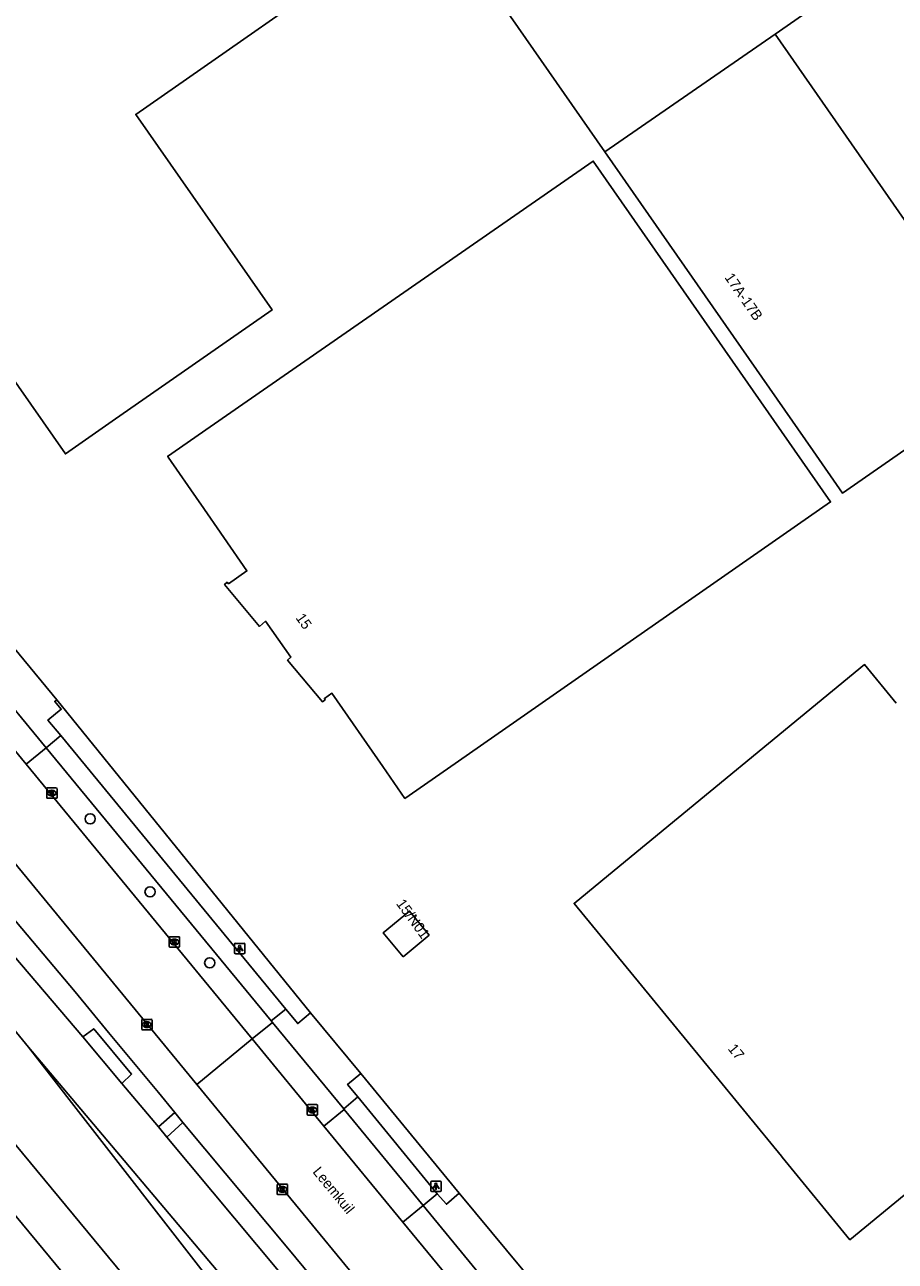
# Model space of a CAD drawing. Extents: x 156651 to 158072, y 387631 to 388990.
# Drawn here: x 157151.7 to 157235.7, y 387850.9 to 387970.3 of the extents above; entities that cross this region are included whole.
import ezdxf

# ---------------------------------------------------------------- set-up
doc = ezdxf.new("R2010")
doc.units = 0
for name, color, linetype in [('IMGEO_Berm_groen', 7, 'Continuous'), ('IMGEO_Boom', 7, 'Continuous'), ('IMGEO_Grasland_overig', 7, 'Continuous'), ('IMGEO_Groenvoorziening', 7, 'Continuous'), ('IMGEO_Kolk', 7, 'Continuous'), ('IMGEO_Lichtpunt', 7, 'Continuous'), ('IMGEO_Muur', 7, 'Continuous'), ('IMGEO_Openbare_ruimte_label', 7, 'Continuous'), ('IMGEO_Pand', 7, 'Continuous'), ('IMGEO_Pand_nummerreeks', 7, 'Continuous'), ('IMGEO_Rijbaan_lokaal_gesloten', 7, 'Continuous'), ('IMGEO_Spoor', 7, 'Continuous'), ('IMGEO_Spoorbaan_halfverhard', 7, 'Continuous'), ('IMGEO_Voetpad_open', 7, 'Continuous')]:
    doc.layers.add(name, color=color, linetype=linetype)

msp = doc.modelspace()

# ---------------------------------------------------------------- linework, layer by layer
at = {"layer": 'IMGEO_Berm_groen'}
for points in [[(157097.86, 387946.26), (157101.16, 387942.42), (157102.79, 387940.5), (157114.27, 387927.11), (157115.96, 387925.21), (157120.79, 387919.43), (157132.18, 387905.88), (157138.68, 387898.17), (157156.55, 387876.96), (157159.78, 387873.03), (157164.59, 387867.23), (157166.18, 387865.29)], [(157166.18, 387865.29), (157166.96, 387864.35)], [(157166.96, 387864.35), (157177.25, 387852.02), (157242.39, 387773.24), (157261.6, 387750), (157335.27, 387660.72)]]:
    msp.add_lwpolyline(points, dxfattribs=at)
at = {"layer": 'IMGEO_Boom'}
for centre in [(157158.01, 387893.65), (157163.79, 387886.6), (157169.55, 387879.75)]:
    msp.add_circle(centre, 0.489, dxfattribs=at)
at = {"layer": 'IMGEO_Grasland_overig'}
for points in [[(157157.31, 387872.59), (157158.35, 387873.39), (157162.01, 387869.01), (157161.07, 387868.11)], [(157164.59, 387863.91), (157166.18, 387865.29)], [(157166.96, 387864.35), (157165.42, 387862.91)]]:
    msp.add_lwpolyline(points, dxfattribs=at)
at = {"layer": 'IMGEO_Groenvoorziening'}
for points in [[(157179.28, 387874.93), (157154.78, 387905.14)], [(157193.64, 387857.52), (157184.13, 387869.06)]]:
    msp.add_lwpolyline(points, dxfattribs=at)
at = {"layer": 'IMGEO_Kolk'}
for p, q in [((157153.81, 387895.71), (157153.81, 387896.56)), ((157153.89, 387896.63), (157154.74, 387896.63)), ((157154.3, 387896.41), (157154.33, 387896.41)), ((157154.81, 387896.56), (157154.81, 387895.71)), ((157154.74, 387895.63), (157153.89, 387895.63)), ((157154.32, 387895.85), (157154.3, 387895.85)), ((157165.64, 387881.34), (157165.64, 387882.19)), ((157165.72, 387882.27), (157166.57, 387882.27)), ((157166.13, 387882.04), (157166.16, 387882.04)), ((157166.64, 387882.19), (157166.64, 387881.34)), ((157166.57, 387881.26), (157165.72, 387881.26)), ((157166.15, 387881.49), (157166.13, 387881.49)), ((157162.98, 387873.36), (157162.98, 387874.22)), ((157163.05, 387874.29), (157163.91, 387874.29)), ((157163.49, 387873.51), (157163.46, 387873.51)), ((157163.47, 387874.07), (157163.49, 387874.07)), ((157163.98, 387874.22), (157163.98, 387873.36)), ((157163.91, 387873.29), (157163.05, 387873.29)), ((157178.96, 387865.13), (157178.96, 387865.98)), ((157179.04, 387866.06), (157179.89, 387866.06)), ((157179.45, 387865.83), (157179.47, 387865.83)), ((157179.47, 387865.28), (157179.45, 387865.28)), ((157179.96, 387865.98), (157179.96, 387865.13)), ((157179.89, 387865.05), (157179.04, 387865.05)), ((157176.07, 387857.45), (157176.07, 387858.31)), ((157176.14, 387858.38), (157177, 387858.38)), ((157176.56, 387858.16), (157176.58, 387858.16)), ((157177.07, 387858.31), (157177.07, 387857.45)), ((157177, 387857.38), (157176.14, 387857.38)), ((157176.58, 387857.6), (157176.55, 387857.6))]:
    msp.add_line(p, q, dxfattribs=at)
for points in [[(157153.81, 387895.71), (157153.81, 387896.56)], [(157153.89, 387896.63), (157154.74, 387896.63)], [(157154.13, 387896.33), (157154.26, 387896.33), (157154.26, 387896.18), (157154.39, 387896.33), (157154.55, 387896.33), (157154.41, 387896.18), (157154.56, 387895.93), (157154.41, 387895.93), (157154.32, 387896.1), (157154.26, 387896.03), (157154.26, 387895.93), (157154.13, 387895.93), (157154.13, 387896.33)], [(157154.81, 387896.56), (157154.81, 387895.71)], [(157154.74, 387895.63), (157153.89, 387895.63)], [(157165.64, 387881.34), (157165.64, 387882.19)], [(157165.72, 387882.27), (157166.57, 387882.27)], [(157165.96, 387881.96), (157166.09, 387881.96), (157166.09, 387881.81), (157166.22, 387881.96), (157166.38, 387881.96), (157166.24, 387881.81), (157166.39, 387881.56), (157166.24, 387881.56), (157166.15, 387881.73), (157166.09, 387881.66), (157166.09, 387881.56), (157165.96, 387881.56), (157165.96, 387881.96)], [(157166.64, 387882.19), (157166.64, 387881.34)], [(157166.57, 387881.26), (157165.72, 387881.26)], [(157162.98, 387873.36), (157162.98, 387874.22)], [(157163.05, 387874.29), (157163.91, 387874.29)], [(157163.3, 387873.99), (157163.42, 387873.99), (157163.42, 387873.84), (157163.55, 387873.99), (157163.72, 387873.99), (157163.57, 387873.84), (157163.72, 387873.59), (157163.57, 387873.59), (157163.49, 387873.76), (157163.42, 387873.69), (157163.42, 387873.59), (157163.3, 387873.59), (157163.3, 387873.99)], [(157163.98, 387874.22), (157163.98, 387873.36)], [(157163.91, 387873.29), (157163.05, 387873.29)], [(157178.96, 387865.13), (157178.96, 387865.98)], [(157179.04, 387866.06), (157179.89, 387866.06)], [(157179.28, 387865.75), (157179.41, 387865.75), (157179.41, 387865.6), (157179.53, 387865.75), (157179.7, 387865.75), (157179.55, 387865.6), (157179.71, 387865.35), (157179.55, 387865.35), (157179.47, 387865.52), (157179.41, 387865.45), (157179.41, 387865.35), (157179.28, 387865.35), (157179.28, 387865.75)], [(157179.96, 387865.98), (157179.96, 387865.13)], [(157179.89, 387865.05), (157179.04, 387865.05)], [(157176.07, 387857.45), (157176.07, 387858.31)], [(157176.14, 387858.38), (157177, 387858.38)], [(157176.39, 387858.08), (157176.51, 387858.08), (157176.51, 387857.93), (157176.64, 387858.08), (157176.81, 387858.08), (157176.66, 387857.93), (157176.81, 387857.68), (157176.66, 387857.68), (157176.58, 387857.84), (157176.51, 387857.78), (157176.51, 387857.68), (157176.39, 387857.68), (157176.39, 387858.08)], [(157177.07, 387858.31), (157177.07, 387857.45)], [(157177, 387857.38), (157176.14, 387857.38)]]:
    msp.add_lwpolyline(points, dxfattribs=at)
for centre, start, end in [((157153.89, 387896.56), 91.552, 178.448), ((157153.89, 387896.56), 91.552, 178.448), ((157154.74, 387896.56), 1.552, 88.448), ((157154.74, 387896.56), 1.552, 88.448), ((157153.89, 387895.71), 181.552, 268.448), ((157153.89, 387895.71), 181.552, 268.448), ((157154.74, 387895.71), 271.552, 358.448), ((157154.74, 387895.71), 271.552, 358.448), ((157165.72, 387882.19), 91.552, 178.448), ((157165.72, 387882.19), 91.552, 178.448), ((157166.57, 387882.19), 1.552, 88.448), ((157166.57, 387882.19), 1.552, 88.448), ((157165.72, 387881.34), 181.552, 268.448), ((157165.72, 387881.34), 181.552, 268.448), ((157166.57, 387881.34), 271.552, 358.448), ((157166.57, 387881.34), 271.552, 358.448), ((157163.06, 387874.22), 91.552, 178.448), ((157163.06, 387874.22), 91.552, 178.448), ((157163.9, 387874.22), 1.552, 88.448), ((157163.9, 387874.22), 1.552, 88.448), ((157163.06, 387873.37), 181.552, 268.448), ((157163.06, 387873.37), 181.552, 268.448), ((157163.9, 387873.37), 271.552, 358.448), ((157163.9, 387873.37), 271.552, 358.448), ((157179.04, 387865.98), 91.552, 178.448), ((157179.04, 387865.98), 91.552, 178.448), ((157179.04, 387865.13), 181.552, 268.448), ((157179.04, 387865.13), 181.552, 268.448), ((157179.89, 387865.98), 1.552, 88.448), ((157179.89, 387865.98), 1.552, 88.448), ((157179.89, 387865.13), 271.552, 358.448), ((157179.89, 387865.13), 271.552, 358.448), ((157176.14, 387858.3), 91.552, 178.448), ((157176.14, 387858.3), 91.552, 178.448), ((157176.99, 387858.3), 1.552, 88.448), ((157176.99, 387858.3), 1.552, 88.448), ((157176.14, 387857.45), 181.552, 268.448), ((157176.14, 387857.45), 181.552, 268.448), ((157176.99, 387857.45), 271.552, 358.448), ((157176.99, 387857.45), 271.552, 358.448)]:
    msp.add_arc(centre, 0.0765, start, end, dxfattribs=at)
for centre, major_axis, ratio, start_param, end_param in [((157154.3, 387896.13), (-0.387, 0.002), 0.722429, 4.712389, 7.853982), ((157154.32, 387896.13), (-0.39, 0.002), 0.717154, 1.570796, 4.712389), ((157166.13, 387881.76), (-0.387, 0.002), 0.722429, 4.712389, 7.853982), ((157166.15, 387881.76), (-0.39, 0.002), 0.717154, 1.570796, 4.712389), ((157163.47, 387873.79), (-0.387, 0.002), 0.722429, 4.712389, 7.853982), ((157163.49, 387873.79), (-0.39, 0.002), 0.717154, 1.570796, 4.712389), ((157179.45, 387865.55), (-0.387, 0.002), 0.722429, 4.712389, 7.853982), ((157179.47, 387865.55), (-0.39, 0.002), 0.717154, 1.570796, 4.712389), ((157176.56, 387857.88), (-0.387, 0.002), 0.722429, 4.712389, 7.853982), ((157176.58, 387857.88), (-0.39, 0.002), 0.717154, 1.570796, 4.712389)]:
    msp.add_ellipse(centre, major_axis=major_axis, ratio=ratio, start_param=start_param, end_param=end_param, dxfattribs=at)
at = {"layer": 'IMGEO_Lichtpunt'}
for p, q in [((157171.94, 387881.54), (157171.94, 387880.73)), ((157171.94, 387881.54), (157171.94, 387880.73)), ((157172.84, 387881.63), (157172.04, 387881.63)), ((157172.84, 387881.63), (157172.04, 387881.63)), ((157172.94, 387880.73), (157172.94, 387881.54)), ((157172.94, 387880.73), (157172.94, 387881.54)), ((157172.04, 387880.63), (157172.84, 387880.63)), ((157172.04, 387880.63), (157172.84, 387880.63)), ((157190.89, 387858.58), (157190.89, 387857.77)), ((157190.89, 387858.58), (157190.89, 387857.77)), ((157191.8, 387858.67), (157190.99, 387858.67)), ((157191.8, 387858.67), (157190.99, 387858.67)), ((157191.89, 387857.77), (157191.89, 387858.58)), ((157191.89, 387857.77), (157191.89, 387858.58)), ((157190.99, 387857.68), (157191.8, 387857.68)), ((157190.99, 387857.68), (157191.8, 387857.68))]:
    msp.add_line(p, q, dxfattribs=at)
for points in [[(157172.32, 387881.2), (157172.35, 387881.17), (157172.17, 387880.91), (157172.13, 387880.94), (157172.32, 387881.2)], [(157172.42, 387881.15), (157172.46, 387881.15), (157172.46, 387880.83), (157172.42, 387880.83), (157172.42, 387881.15)], [(157172.53, 387881.17), (157172.57, 387881.2), (157172.75, 387880.94), (157172.71, 387880.91), (157172.53, 387881.17)], [(157191.27, 387858.24), (157191.31, 387858.21), (157191.12, 387857.95), (157191.08, 387857.98), (157191.27, 387858.24)], [(157191.37, 387858.19), (157191.42, 387858.19), (157191.42, 387857.87), (157191.37, 387857.87), (157191.37, 387858.19)], [(157191.48, 387858.21), (157191.52, 387858.24), (157191.7, 387857.98), (157191.67, 387857.95), (157191.48, 387858.21)]]:
    msp.add_lwpolyline(points, dxfattribs=at)
for centre in [(157172.44, 387881.33), (157191.39, 387858.38)]:
    msp.add_circle(centre, 0.0994, dxfattribs=at)
for centre, start, end in [((157172.04, 387881.54), 90, 180), ((157172.04, 387881.54), 90, 180), ((157172.04, 387880.73), 180, 270), ((157172.04, 387880.73), 180, 270), ((157172.84, 387881.54), 0, 90), ((157172.84, 387881.54), 0, 90), ((157172.84, 387880.73), 270, 0), ((157172.84, 387880.73), 270, 360), ((157190.99, 387858.58), 90, 180), ((157190.99, 387858.58), 90, 180), ((157191.8, 387858.58), 0, 90), ((157191.8, 387858.58), 0, 90), ((157190.99, 387857.77), 180, 270), ((157190.99, 387857.77), 180, 270), ((157191.8, 387857.77), 270, 0), ((157191.8, 387857.77), 270, 360)]:
    msp.add_arc(centre, 0.0946, start, end, dxfattribs=at)
at = {"layer": 'IMGEO_Muur'}
msp.add_lwpolyline([(157157.31, 387872.59), (157158.35, 387873.39), (157162.01, 387869.01), (157161.07, 387868.11)], dxfattribs=at)
at = {"layer": 'IMGEO_Pand'}
for points in [[(157207.7, 387958.03), (157179.19, 387998.98), (157178.48, 388000), (157176.33, 388003.09), (157176.56, 388003.25), (157177.55, 388001.86), (157179.69, 388003.34), (157179.28, 388003.91), (157184.93, 388007.86), (157185.35, 388007.27), (157187.15, 388006.98), (157196.91, 388013.77), (157197.32, 388013.14), (157199.1, 388012.91), (157199.69, 388013.26), (157202.55, 388009.16), (157205.13, 388005.44), (157208.92, 388000), (157219.55, 387984.75), (157223.61, 387987.58), (157232.26, 387975.15), (157228.2, 387972.32), (157228.25, 387972.25), (157224.14, 387969.38)], [(157176.45, 387993.48), (157173.58, 387997.58), (157129.48, 387966.8), (157128.3, 387968.4), (157121.58, 387963.7), (157125.43, 387958.16), (157126.22, 387958.72), (157128.51, 387955.46), (157127.71, 387954.91), (157132.32, 387948.3), (157138.87, 387952.87), (157155.62, 387928.88), (157160.14, 387932.03), (157175.57, 387942.78), (157162.4, 387961.64), (157186.78, 387978.67), (157176.45, 387993.48)], [(157207.7, 387958.03), (157227.79, 387929.18), (157230.65, 387925.08), (157246.8, 387936.32), (157247.06, 387936.51), (157244.2, 387940.61), (157224.14, 387969.38)], [(157224.14, 387969.38), (157207.7, 387958.03)], [(157192.5, 387898.48), (157229.49, 387924.24), (157206.58, 387957.15), (157169.58, 387931.49), (157165.48, 387928.64), (157165.54, 387928.55), (157168.52, 387924.24), (157168.68, 387924.02), (157173.14, 387917.58), (157171.37, 387916.35), (157171.22, 387916.49), (157170.99, 387916.28), (157174.37, 387912.23), (157174.94, 387912.73), (157177.38, 387909.27), (157177.07, 387908.98), (157180.45, 387904.94), (157180.69, 387905.15), (157180.62, 387905.27), (157181.34, 387905.77), (157186.26, 387898.69), (157188.39, 387895.62), (157192.5, 387898.48)], [(157235.82, 387904.8), (157232.77, 387908.54), (157208.59, 387888.67), (157204.73, 387885.49), (157211.24, 387877.55), (157224.74, 387861.08), (157224.82, 387860.98), (157231.35, 387853.02), (157259.41, 387876.08), (157259.35, 387876.16), (157258.41, 387877.3)], [(157188.22, 387880.33), (157190.73, 387882.42), (157188.84, 387884.75), (157186.3, 387882.65), (157188.22, 387880.33)]]:
    msp.add_lwpolyline(points, dxfattribs=at)
at = {"layer": 'IMGEO_Rijbaan_lokaal_gesloten'}
for points in [[(157168.3, 387867.99), (157086.65, 387967.25)], [(157151.82, 387898.92), (157135.3, 387919)], [(157173.66, 387872.4), (157151.82, 387898.92)], [(157168.3, 387867.99), (157173.66, 387872.4)], [(157180.58, 387863.99), (157173.66, 387872.4)], [(157337.84, 387661.89), (157244.68, 387775.14), (157168.3, 387867.99)], [(157188.2, 387854.73), (157180.58, 387863.99)], [(157197.68, 387843.21), (157188.2, 387854.73)]]:
    msp.add_lwpolyline(points, dxfattribs=at)
at = {"layer": 'IMGEO_Spoor'}
for points in [[(156872.42, 388201.34), (156882.92, 388187.99), (156900.38, 388166.18), (156921.46, 388140.64), (156943.25, 388114.61), (156960.21, 388094.66), (156986.26, 388064.32), (157082.58, 387953.12), (157127.58, 387900.65), (157147.69, 387876.91), (157152.06, 387871.62)], [(156869.11, 388198.61), (156881.13, 388183.36), (156896.99, 388163.69), (156934.03, 388118.81), (156947.9, 388102.26), (156968.65, 388077.78), (157013.93, 388024.81), (157050.91, 387981.41), (157095.66, 387928.29), (157129.46, 387887.97), (157178.38, 387828.84), (157215.76, 387783.49)], [(156865.31, 388195.46), (156870.02, 388189.51), (156887.81, 388167.44), (156909.51, 388141.18), (156951.28, 388091.52), (156994.8, 388040.34), (157047.71, 387978.3), (157077.25, 387943.43), (157106.48, 387908.59), (157145.62, 387861.58), (157233.33, 387755.47), (157295.4, 387680.68)], [(157152.06, 387871.62), (157181.04, 387834.3)], [(157152.06, 387871.62), (157182.53, 387835.51)]]:
    msp.add_lwpolyline(points, dxfattribs=at)
at = {"layer": 'IMGEO_Spoorbaan_halfverhard'}
for points in [[(157157.31, 387872.59), (157123.95, 387911.7), (157068.12, 387976.85), (157042.81, 388006.06), (156962.41, 388099.5), (156929.1, 388138.77), (156911.81, 388159.68), (156885.92, 388191.4), (156881.34, 388197.23)], [(157161.07, 387868.11), (157157.31, 387872.59)], [(157164.59, 387863.91), (157161.07, 387868.11)], [(157165.42, 387862.91), (157164.59, 387863.91)], [(157345.11, 387646.08), (157317.79, 387679.06), (157284.83, 387719.06), (157252.18, 387758.51), (157223.1, 387793.91), (157216.02, 387802.1), (157185.01, 387839.47), (157165.42, 387862.91)]]:
    msp.add_lwpolyline(points, dxfattribs=at)
at = {"layer": 'IMGEO_Voetpad_open'}
for points in [[(157137.23, 387920.59), (157153.75, 387900.51)], [(157154.78, 387905.14), (157141.56, 387921.14)], [(157154.78, 387905.14), (157154.59, 387904.99), (157155.22, 387904.23), (157153.93, 387903.18), (157155.16, 387901.68)], [(157155.16, 387901.68), (157153.75, 387900.51)], [(157155.16, 387901.68), (157176.89, 387875.27)], [(157153.75, 387900.51), (157151.82, 387898.92)], [(157175.47, 387874.14), (157153.75, 387900.51)], [(157176.89, 387875.27), (157175.47, 387874.14)], [(157179.28, 387874.93), (157178.05, 387873.88), (157176.89, 387875.27)], [(157184.13, 387869.06), (157179.28, 387874.93)], [(157175.6, 387873.99), (157173.66, 387872.4)], [(157175.47, 387874.14), (157175.6, 387873.99)], [(157182.48, 387865.65), (157175.6, 387873.99)], [(157183.85, 387866.8), (157182.86, 387868.02), (157184.13, 387869.06)], [(157183.85, 387866.8), (157182.48, 387865.65)], [(157191.52, 387857.46), (157183.85, 387866.8)], [(157180.58, 387863.99), (157182.52, 387865.6)], [(157182.52, 387865.6), (157182.48, 387865.65)], [(157190.15, 387856.33), (157182.52, 387865.6)], [(157190.15, 387856.33), (157191.52, 387857.46)], [(157191.52, 387857.46), (157192.4, 387856.44), (157193.64, 387857.52)], [(157201.35, 387848.22), (157193.64, 387857.52)], [(157188.2, 387854.73), (157190.15, 387856.33)], [(157199.62, 387844.8), (157190.15, 387856.33)]]:
    msp.add_lwpolyline(points, dxfattribs=at)

# ---------------------------------------------------------------- texts
at = {"layer": 'IMGEO_Openbare_ruimte_label'}
msp.add_text('Leemkuil', height=1, rotation=309.4386, dxfattribs=at).set_placement((157179.43, 387859.55))
at = {"layer": 'IMGEO_Pand_nummerreeks'}
for s, rotation, p in [('17A-17B', 304.8528, (157219.21, 387945.91)), ('15', 305.2023, (157177.8, 387913.05)), ('15/N01', 306.0274, (157187.5, 387885.46)), ('17', 309.3448, (157219.52, 387871.43))]:
    msp.add_text(s, height=1, rotation=rotation, dxfattribs=at).set_placement(p)

doc.saveas('drawing.dxf')
